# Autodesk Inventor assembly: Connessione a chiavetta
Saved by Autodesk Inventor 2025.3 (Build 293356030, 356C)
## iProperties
ClientObjectVersion: 1
Created: 2026-05
Part Number: Connessione a chiavetta
Document SubType Name: Assembly
Designer: R5800u
Author: R5800u
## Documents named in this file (1)
- C:\Users\R5800u\Desktop\riduttore_pompa2\Connessione a chiavetta5.iam
